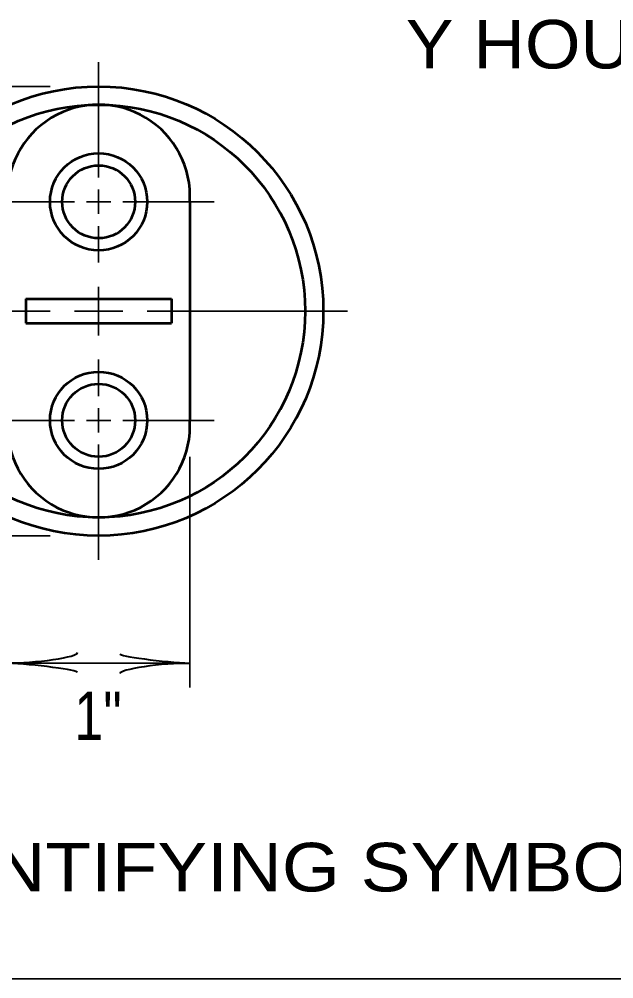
# Model space of a CAD drawing. Extents: x -1 to 679, y 0 to 440.
# Drawn here: x 85.12 to 109.6, y 135.76 to 175.28 of the extents above; entities that cross this region are included whole.
import ezdxf

# ---------------------------------------------------------------- set-up
doc = ezdxf.new("R2010")
doc.units = 0
doc.header["$LTSCALE"] = 0.8
doc.layers.add('1', color=7, linetype='Continuous', lineweight=53)

msp = doc.modelspace()

# ---------------------------------------------------------------- linework, layer by layer
at = {"layer": '1', "lineweight": 35}
for p, q in [((88.3878, 173.5118), (88.3878, 168.7618)), ((86.3878, 172.5118), (68.3878, 172.5118)), ((88.3878, 168.2618), (88.3878, 167.2618)), ((74.3062, 167.7618), (87.3878, 167.7618)), ((87.8878, 167.7618), (88.8878, 167.7618)), ((89.3878, 167.7618), (93.1378, 167.7618)), ((88.3878, 166.7618), (88.3878, 165.2618)), ((78.1378, 163.2618), (86.3878, 163.2618)), ((90.3878, 163.2618), (98.6378, 163.2618)), ((88.3878, 161.2618), (88.3878, 159.7618)), ((88.3878, 159.2618), (88.3878, 158.2618)), ((74.3062, 158.7618), (87.3878, 158.7618)), ((87.8878, 158.7618), (88.8878, 158.7618)), ((89.3878, 158.7618), (93.1378, 158.7618)), ((88.3878, 157.7618), (88.3878, 153.0118)), ((92.1378, 157.2618), (92.1378, 147.7618)), ((86.3878, 154.0118), (68.3878, 154.0118)), ((84.6378, 148.7618), (92.1378, 148.7618)), ((122.1378, 135.7618), (79.8449, 135.7618))]:
    msp.add_line(p, q, dxfattribs=at)
at = {"layer": '1'}
for p, q in [((92.1378, 167.7618), (92.1378, 163.2618)), ((85.3878, 163.7618), (88.3878, 163.7618)), ((85.3878, 163.7618), (85.3878, 162.7618)), ((88.3878, 163.7618), (91.3878, 163.7618)), ((91.3878, 163.7618), (91.3878, 162.7618)), ((92.1378, 163.2618), (92.1378, 158.7618)), ((85.3878, 162.7618), (88.3878, 162.7618)), ((88.3878, 162.7618), (91.3878, 162.7618))]:
    msp.add_line(p, q, dxfattribs=at)
at = {"layer": '1', "lineweight": 35}
for points in [[(88.3878, 164.2618), (88.3878, 163.2618), (88.3878, 162.2618)], [(87.3878, 163.2618), (88.3878, 163.2618), (89.3878, 163.2618)]]:
    msp.add_lwpolyline(points, dxfattribs=at)
at = {"layer": '1'}
for centre, radius in [((88.3878, 163.2618), 9.25), ((88.3878, 163.2618), 8.5), ((88.3878, 167.7618), 2), ((88.3878, 167.7618), 1.5), ((88.3878, 158.7618), 2), ((88.3878, 158.7618), 1.5)]:
    msp.add_circle(centre, radius, dxfattribs=at)
for centre, start, end in [((88.3878, 168.0039), 356.30478, 183.69522), ((88.3878, 158.5196), 176.30478, 3.69522)]:
    msp.add_arc(centre, 3.7578, start, end, dxfattribs=at)
at = {"layer": '1', "lineweight": 40}
for centre, major_axis, ratio, start_param, end_param in [((85.729, 149.038), (-1.7857, -0.1562), 0.122415, 0.8963533, 3.1415927), ((85.729, 149.038), (-1.7857, -0.1562), 0.122415, 0.8963533, 3.1415927), ((91.0173, 148.9734), (1.7565, -0.1757), 0.07063, 3.1407148, 5.41811), ((85.7583, 148.5501), (-1.7565, 0.1757), 0.07063, 3.1407148, 5.41811), ((85.7583, 148.5501), (-1.7565, 0.1757), 0.07063, 3.1407148, 5.41811), ((91.0466, 148.4855), (1.7857, 0.1562), 0.122415, 0.8963533, 3.1415927)]:
    msp.add_ellipse(centre, major_axis=major_axis, ratio=ratio, start_param=start_param, end_param=end_param, dxfattribs=at)

# ---------------------------------------------------------------- texts
at = {"layer": '1'}
for s, width, p in [('Y HOUSING', 1.1, (101.0351, 173.2527)), ('1"', 0.8, (87.3879, 145.5935)), ('IDENTIFYING SYMBOLS IV', 1.15, (78.8437, 139.3612))]:
    msp.add_text(s, height=2, dxfattribs=dict(at, width=width)).set_placement(p)

doc.saveas('drawing.dxf')
